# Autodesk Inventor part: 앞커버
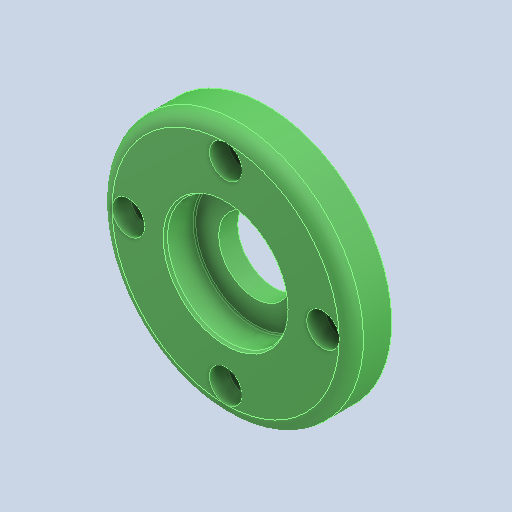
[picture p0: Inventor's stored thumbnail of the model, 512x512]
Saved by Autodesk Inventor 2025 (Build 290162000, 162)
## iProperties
Created: 2024-07
Part Number: 앞커버
Material: 알루미늄 6061
Document SubType Name: Modeling
Designer: samsung
Density: 2.71 g/cm^3
Appearance: 기본값
Author: jhkim
Sending System: Autodesk Inventor 2025
Preprocessor: ST-DEVELOPER v20
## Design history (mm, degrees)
feature "솔리드1"
node "솔리드2"
